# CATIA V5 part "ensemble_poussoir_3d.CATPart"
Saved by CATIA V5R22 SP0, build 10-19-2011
Part number: Poussoir_flacon
Bounding box of the stored display mesh (mm): x 0 to 187, y 0 to 48, z 0 to 49
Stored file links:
  C:\Users\La forge\Desktop\CAO_PER_pick&place_2023A\Sous_Ensemble_Flacon\Verin\Poussoir_Flacon\ensemble_poussoir_3d.CATPart
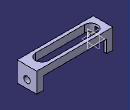
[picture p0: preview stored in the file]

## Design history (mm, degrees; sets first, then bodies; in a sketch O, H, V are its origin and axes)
Body1 (main body)
  Sketch1 on yz-plane, origin (0, 0, 0), H (0, 1, 0), V (0, 0, 1)
    line L1 (0, 0) -> (48, 0)
    line L2 (48, 0) -> (48, 49)
    line L3 (48, 49) -> (0, 49)
    line L4 (0, 49) -> (0, 0)
    point P1 (48, 0)
    point P2 (48, 49)
    point P3 (0, 49)
    distance P1 P2 = 49
    distance P2 P3 = 48
    horizontal: L1 H, L3 H
    vertical: L2 V, L4 V
  Pad1: profile Sketch1, direction (1, 0, 0), length 187
  Sketch2 on face of Pad1 from Sketch1.L4, origin (0, 0, 0), H (1, 0, 0), V (0, 0, 1)
    point P1 (15, 0)
    line L1 (15, 0) -> (170, 0)
    line L2 (170, 0) -> (170, 31)
    line L3 (170, 31) -> (15, 31)
    line L4 (15, 31) -> (15, 0)
    reference projected line E1 (0, 49) -> (187, 49) from edge [face of Pad1 from Sketch1.L4 | face of Pad1 from Sketch1.L3]
    reference projected line E2 (187, 49) -> (187, 0) from edge [face of Pad1 from Sketch1.L4 | end face of Pad1]
    reference projected line E3 (0, 49) -> (0, 0) from edge [start face of Pad1 | face of Pad1 from Sketch1.L4]
    distance L3 E1 = 18
    distance L2 E2 = 17
    distance L4 E3 = 15
    coincidence: P1 H
    horizontal: L1 H, L3 H
    vertical: L2 V, L4 V
  Pocket1: profile Sketch2, direction (0, 1, 0), through (limit type 3)
  Sketch3 on start face of Pad1, origin (0, 0, 0), H (0, -1, 0), V (0, 0, 1)
    line L1 (-41, 0) -> (-7, 0)
    line L2 (-7, 0) -> (-7, 31.5)
    line L3 (-41, 31.5) -> (-41, 0)
    point P2 (-7, 0)
    point P3 (-7, 49)
    point P4 (-41, 49)
    reference projected line E1 (0, 49) -> (0, 0) from edge [start face of Pad1 | face of Pad1 from Sketch1.L4]
    reference projected line E2 (-48, 0) -> (-48, 49) from edge [start face of Pad1 | face of Pad1 from Sketch1.L2]
    reference projected line E3 (0, 0) -> (-48, 0) from edge [start face of Pad1 | face of Pad1 from Sketch1.L1]
    point P5 (-7, 31.5)
    point P6 (-41, 31.5)
    arc A1 centre (-24, 25.5839) radius 18 from (-7, 31.5) to (-41, 31.5) ccw
    point P8 (-7, 31.5)
    point P9 (-41, 31.5)
    distance L2 E1 = 7
    distance L3 E2 = 7
    length L3 = 31.5
    radius A1 = 18
    distance P5 P2 = 31.5
    horizontal: L1 H
    vertical: L2 V, L3 V
    coincidence: E3 L1, L3 P6, L2 P5, P5 P8, P6 P9
  Pocket2: profile Sketch3, direction (1, 0, 0), up to face of Pocket1 from Sketch2.L4
  Sketch4 on face of Pad1 from Sketch1.L3, origin (0, 0, 49), H (1, 0, 0), V (0, 1, 0)
    point P1 (90, 24)
    line L1 (150, 8) -> (30, 8)
    line L2 (30, 40) -> (150, 40)
    point P3 (150, 8)
    point P4 (30, 8)
    arc A1 centre (150, 24) radius 16 from (150, 40) to (150, 8) cw
    arc A2 centre (30, 24) radius 16 from (30, 8) to (30, 40) cw
    distance L1 L2 = 32
    distance P3 P4 = 120
    radius A1 = 16
    radius A2 = 16
    horizontal: L1 H, L2 H
    equidistance: L1 L2 P1
    fix: P1
  Pocket3: profile Sketch4, direction (0, 0, -1), through (limit type 3)
  Sketch5 on face of Pocket1 from Sketch2.L2, origin (170, 0, 0), H (0, 1, 0), V (0, 0, 1)
    circle A1 centre (24, 19.25) radius 4.25
    point P1 (24, 19.25)
    reference projected line E1 (48, 0) -> (48, 49) from edge [face of Pad1 from Sketch1.L2 | end face of Pad1]
    reference projected line E2 (0, 0) -> (48, 0) from edge [face of Pad1 from Sketch1.L1 | end face of Pad1]
    distance P1 E1 = 24
    radius A1 = 4.25
    distance A1 E2 = 15
  Pocket4: profile Sketch5, direction (1, 0, 0), length 5
  Sketch6 on end face of Pad1, origin (187, 0, 0), H (0, 1, 0), V (0, 0, 1)
    circle A1 centre (24, 19.25) radius 8
    reference projected circle E1 centre (24, 19.25) radius 4.25 from Sketch5.A1
    radius A1 = 8
    concentricity: E1 A1
  Pocket5: profile Sketch6, direction (-1, 0, 0), length 12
